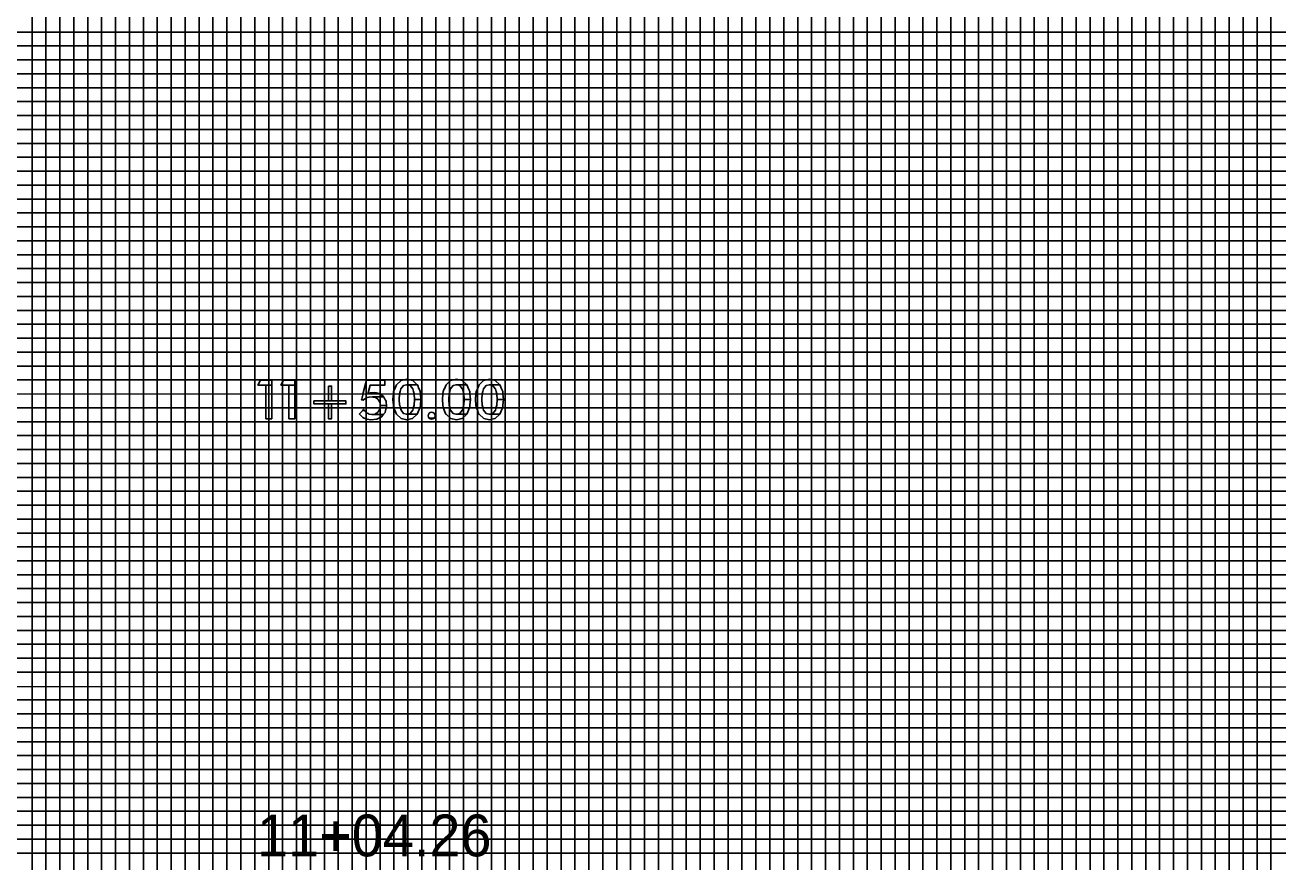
# Model space of a CAD drawing. Extents: x -13 to 323, y -5 to 1431.
# Drawn here: x 134.5 to 224.5, y 44.4 to 104.5 of the extents above; entities that cross this region are included whole.
import ezdxf

# ---------------------------------------------------------------- set-up
doc = ezdxf.new("R2010")
doc.units = 0
for name, color, linetype in [('Prop XS Station Labels', 7, 'Continuous'), ('Scratch_Level_3', 7, 'Continuous'), ('Sheet Cross Section Grid Major CELL', 7, 'Continuous'), ('Sheet Cross Section Grid Middle CELL', 7, 'Continuous'), ('Sheet Cross Section Grid Minor 1 CELL', 7, 'Continuous'), ('Sheet Cross Section Grid Minor 2 CELL', 7, 'Continuous'), ('Sheet DOT Grid CELL', 7, 'Continuous')]:
    doc.layers.add(name, color=color, linetype=linetype)

msp = doc.modelspace()

# ---------------------------------------------------------------- linework, layer by layer
at = {"layer": 'Prop XS Station Labels'}
for points in [[(151.405, 78.994), (151.226, 78.63), (152.224, 78.63), (152.224, 78.994)], [(151.805, 78.63), (151.805, 76.213), (152.224, 76.213), (152.224, 78.63)], [(153.059, 78.994), (152.881, 78.63), (153.878, 78.63), (153.878, 78.994)], [(153.46, 78.63), (153.46, 76.213), (153.878, 76.213), (153.878, 78.63)], [(156.291, 78.554), (156.291, 77.497), (156.518, 77.497), (156.518, 78.554)], [(158.679, 77.592), (158.674, 77.568), (158.814, 77.568), (158.84, 77.592), (158.873, 77.621), (159.015, 77.706), (159.078, 77.726), (159.218, 77.77), (159.447, 77.783), (160.263, 77.783), (160.246, 77.813), (159.978, 78.003), (159.135, 78.003), (159.141, 78.029), (159.141, 78.029), (159.151, 78.068), (159.3, 78.625), (160.351, 78.625), (160.351, 78.994), (159.025, 78.994), (158.934, 78.625), (158.796, 78.068), (158.787, 78.029), (158.78, 78.003), (158.734, 77.813), (158.726, 77.783), (158.723, 77.77), (158.712, 77.726), (158.707, 77.706), (158.686, 77.621)], [(161.527, 76.222), (161.926, 76.14), (162.315, 76.222), (162.337, 76.226), (162.668, 76.53), (161.92, 76.53), (161.9, 76.535), (161.891, 76.538), (161.682, 76.597), (161.507, 76.823), (161.507, 76.825), (161.506, 76.825), (161.451, 77.027), (161.45, 77.031), (161.41, 77.176), (161.408, 77.185), (161.373, 77.59), (161.373, 77.594), (161.373, 77.599), (161.408, 78.003), (161.45, 78.156), (161.45, 78.161), (161.504, 78.357), (161.505, 78.363), (161.682, 78.592), (161.907, 78.651), (161.915, 78.653), (161.935, 78.658), (162.675, 78.658), (162.349, 78.957), (162.332, 78.961), (161.931, 79.049), (161.93, 79.049), (161.515, 78.961), (161.51, 78.957), (161.188, 78.658), (161.182, 78.653), (161.18, 78.651), (161.155, 78.592), (161.061, 78.363), (161.059, 78.357), (160.978, 78.161), (160.977, 78.156), (160.961, 78.003), (160.919, 77.599), (160.918, 77.594), (160.919, 77.59), (160.959, 77.185), (160.96, 77.176), (160.975, 77.031), (160.975, 77.027), (161.058, 76.825), (161.059, 76.823), (161.151, 76.597), (161.175, 76.538), (161.176, 76.535), (161.182, 76.53), (161.522, 76.226)], [(162.449, 78.003), (162.482, 77.599), (162.936, 77.599), (162.896, 78.003), (162.882, 78.156), (162.88, 78.161), (162.88, 78.161), (162.801, 78.357), (162.8, 78.357), (162.798, 78.363), (162.706, 78.592), (162.706, 78.592), (162.682, 78.651), (162.682, 78.653), (162.675, 78.658), (161.935, 78.658), (161.955, 78.653), (161.961, 78.651), (162.175, 78.592), (162.35, 78.363), (162.355, 78.357), (162.407, 78.161), (162.408, 78.156)], [(165.086, 76.222), (165.485, 76.14), (165.875, 76.222), (165.896, 76.226), (166.227, 76.53), (165.479, 76.53), (165.46, 76.535), (165.45, 76.538), (165.241, 76.597), (165.066, 76.823), (165.066, 76.825), (165.065, 76.825), (165.01, 77.027), (165.01, 77.031), (164.97, 77.176), (164.967, 77.185), (164.932, 77.59), (164.932, 77.594), (164.932, 77.599), (164.967, 78.003), (165.009, 78.156), (165.01, 78.161), (165.063, 78.357), (165.065, 78.363), (165.241, 78.592), (165.466, 78.651), (165.474, 78.653), (165.495, 78.658), (166.235, 78.658), (165.908, 78.957), (165.891, 78.961), (165.49, 79.049), (165.49, 79.049), (165.074, 78.961), (165.07, 78.957), (164.747, 78.658), (164.741, 78.653), (164.739, 78.651), (164.715, 78.592), (164.62, 78.363), (164.618, 78.357), (164.537, 78.161), (164.536, 78.156), (164.52, 78.003), (164.478, 77.599), (164.477, 77.594), (164.478, 77.59), (164.518, 77.185), (164.519, 77.176), (164.534, 77.031), (164.535, 77.027), (164.617, 76.825), (164.618, 76.823), (164.71, 76.597), (164.734, 76.538), (164.735, 76.535), (164.741, 76.53), (165.081, 76.226)], [(166.008, 78.003), (166.041, 77.599), (166.495, 77.599), (166.455, 78.003), (166.441, 78.156), (166.439, 78.161), (166.439, 78.161), (166.36, 78.357), (166.36, 78.357), (166.357, 78.363), (166.265, 78.592), (166.265, 78.592), (166.241, 78.651), (166.241, 78.653), (166.235, 78.658), (165.495, 78.658), (165.514, 78.653), (165.52, 78.651), (165.734, 78.592), (165.909, 78.363), (165.914, 78.357), (165.966, 78.161), (165.967, 78.156)], [(167.459, 76.222), (167.858, 76.14), (168.247, 76.222), (168.269, 76.226), (168.6, 76.53), (167.852, 76.53), (167.832, 76.535), (167.823, 76.538), (167.614, 76.597), (167.439, 76.823), (167.439, 76.825), (167.438, 76.825), (167.383, 77.027), (167.382, 77.031), (167.342, 77.176), (167.34, 77.185), (167.305, 77.59), (167.305, 77.594), (167.305, 77.599), (167.34, 78.003), (167.381, 78.156), (167.382, 78.161), (167.435, 78.357), (167.437, 78.363), (167.614, 78.592), (167.839, 78.651), (167.846, 78.653), (167.867, 78.658), (168.607, 78.658), (168.281, 78.957), (168.264, 78.961), (167.863, 79.049), (167.862, 79.049), (167.446, 78.961), (167.442, 78.957), (167.12, 78.658), (167.114, 78.653), (167.112, 78.651), (167.087, 78.592), (166.993, 78.363), (166.99, 78.357), (166.91, 78.161), (166.909, 78.156), (166.893, 78.003), (166.85, 77.599), (166.85, 77.594), (166.85, 77.59), (166.891, 77.185), (166.892, 77.176), (166.907, 77.031), (166.907, 77.027), (166.99, 76.825), (166.99, 76.823), (167.083, 76.597), (167.107, 76.538), (167.108, 76.535), (167.114, 76.53), (167.454, 76.226)], [(168.381, 78.003), (168.414, 77.599), (168.868, 77.599), (168.828, 78.003), (168.814, 78.156), (168.812, 78.161), (168.811, 78.161), (168.733, 78.357), (168.732, 78.357), (168.73, 78.363), (168.638, 78.592), (168.638, 78.592), (168.614, 78.651), (168.614, 78.653), (168.607, 78.658), (167.867, 78.658), (167.887, 78.653), (167.893, 78.651), (168.106, 78.592), (168.281, 78.363), (168.286, 78.357), (168.339, 78.161), (168.34, 78.156)], [(155.255, 77.497), (155.255, 77.27), (157.554, 77.27), (157.554, 77.497)], [(158.673, 77.568), (158.789, 77.545), (158.814, 77.568)], [(159.21, 78.029), (159.135, 78.003), (159.978, 78.003), (159.942, 78.029), (159.746, 78.068), (159.325, 78.068)], [(159.6, 78.097), (159.325, 78.068), (159.746, 78.068), (159.601, 78.097)], [(159.991, 77.394), (160.035, 77.154), (160.46, 77.154), (160.439, 77.394), (160.439, 77.394), (160.432, 77.475), (160.393, 77.545), (160.381, 77.568), (160.368, 77.592), (160.352, 77.621), (160.305, 77.706), (160.294, 77.726), (160.27, 77.77), (160.263, 77.783), (159.447, 77.783), (159.5, 77.77), (159.682, 77.726), (159.71, 77.706), (159.831, 77.621), (159.873, 77.592), (159.887, 77.568), (159.9, 77.545), (159.942, 77.475)], [(161.94, 76.535), (161.92, 76.53), (162.668, 76.53), (162.674, 76.535), (162.677, 76.538), (162.701, 76.597), (162.795, 76.823), (162.796, 76.825), (162.879, 77.027), (162.881, 77.031), (162.895, 77.176), (162.896, 77.185), (162.936, 77.59), (162.936, 77.594), (162.936, 77.599), (162.481, 77.599), (162.481, 77.594), (162.481, 77.59), (162.449, 77.185), (162.448, 77.176), (162.409, 77.031), (162.408, 77.027), (162.354, 76.825), (162.352, 76.823), (162.175, 76.597), (161.951, 76.538)], [(165.5, 76.535), (165.479, 76.53), (166.227, 76.53), (166.233, 76.535), (166.236, 76.538), (166.26, 76.597), (166.354, 76.823), (166.355, 76.825), (166.438, 77.027), (166.44, 77.031), (166.454, 77.176), (166.455, 77.185), (166.495, 77.59), (166.495, 77.594), (166.495, 77.599), (166.04, 77.599), (166.04, 77.594), (166.04, 77.59), (166.008, 77.185), (166.007, 77.176), (165.968, 77.031), (165.967, 77.027), (165.913, 76.825), (165.911, 76.823), (165.734, 76.597), (165.51, 76.538)], [(167.872, 76.535), (167.852, 76.53), (168.6, 76.53), (168.606, 76.535), (168.609, 76.538), (168.633, 76.597), (168.727, 76.823), (168.728, 76.825), (168.811, 77.027), (168.813, 77.031), (168.827, 77.176), (168.828, 77.185), (168.868, 77.59), (168.868, 77.594), (168.868, 77.599), (168.413, 77.599), (168.413, 77.594), (168.413, 77.59), (168.38, 77.185), (168.38, 77.176), (168.34, 77.031), (168.34, 77.027), (168.285, 76.825), (168.284, 76.823), (168.106, 76.597), (167.883, 76.538)], [(156.291, 77.27), (156.291, 76.213), (156.518, 76.213), (156.518, 77.27)], [(159.077, 76.179), (159.348, 76.14), (159.744, 76.179), (159.76, 76.187), (160.007, 76.307), (160.007, 76.307), (160.106, 76.355), (160.195, 76.463), (160.234, 76.511), (159.411, 76.511), (159.192, 76.549), (159.188, 76.551), (159.183, 76.553), (159.017, 76.645), (158.997, 76.666), (158.985, 76.678), (158.985, 76.678), (158.884, 76.783), (158.819, 76.883), (158.819, 76.883), (158.728, 76.783), (158.634, 76.678), (158.623, 76.666), (158.604, 76.645), (158.521, 76.553), (158.519, 76.551), (158.52, 76.549), (158.551, 76.511), (158.589, 76.463), (158.716, 76.355), (158.773, 76.307), (159.021, 76.187)], [(159.625, 76.549), (159.411, 76.511), (160.234, 76.511), (160.265, 76.549), (160.266, 76.551), (160.269, 76.553), (160.268, 76.553), (160.344, 76.645), (160.361, 76.666), (160.364, 76.678), (160.393, 76.783), (160.423, 76.893), (160.469, 77.06), (160.46, 77.154), (160.035, 77.154), (160.019, 77.06), (159.99, 76.893), (159.92, 76.783), (159.853, 76.678), (159.833, 76.666), (159.8, 76.645), (159.651, 76.553), (159.635, 76.551)], [(163.475, 76.331), (163.529, 76.25), (163.885, 76.25), (163.938, 76.331), (163.957, 76.426), (163.938, 76.523), (163.885, 76.603), (163.803, 76.657), (163.706, 76.676), (163.61, 76.657), (163.529, 76.603), (163.475, 76.523), (163.455, 76.426)], [(163.61, 76.194), (163.706, 76.176), (163.803, 76.194), (163.885, 76.25), (163.529, 76.25)]]:
    msp.add_lwpolyline(points, close=True, dxfattribs=at)
at = {"layer": 'Scratch_Level_3'}
for points in [[(20, 110), (300, 110), (300, 80), (20, 80)], [(20, 75), (300, 75), (300, 45), (20, 45)]]:
    msp.add_lwpolyline(points, close=True, dxfattribs=at)
at = {"layer": 'Sheet Cross Section Grid Major CELL'}
for p, q in [((140, 210), (140, 0)), ((150, 0), (150, 210)), ((160, 210), (160, 0)), ((170, 0), (170, 210)), ((180, 210), (180, 0)), ((190, 0), (190, 210)), ((200, 210), (200, 0)), ((210, 0), (210, 210)), ((220, 210), (220, 0))]:
    msp.add_line(p, q, dxfattribs=at)
for points in [[(0, 100), (320, 100), (320, 90), (0, 90)], [(0, 80), (320, 80), (320, 70), (0, 70)], [(0, 60), (320, 60), (320, 50), (0, 50)]]:
    msp.add_lwpolyline(points, dxfattribs=at)
at = {"layer": 'Sheet Cross Section Grid Middle CELL'}
for points in [[(125, 0), (135, 0), (135, 210)], [(145, 210), (145, 0), (155, 0), (155, 210)], [(165, 210), (165, 0), (175, 0), (175, 210)], [(185, 210), (185, 0), (195, 0), (195, 210)], [(205, 210), (205, 0), (215, 0), (215, 210)], [(0, 85), (320, 85), (320, 95), (0, 95)], [(0, 65), (320, 65), (320, 75), (0, 75)], [(0, 45), (320, 45), (320, 55), (0, 55)]]:
    msp.add_lwpolyline(points, dxfattribs=at)
at = {"layer": 'Sheet Cross Section Grid Minor 1 CELL'}
for points in [[(0, 104), (320, 104), (320, 103), (0, 103)], [(0, 102), (320, 102), (320, 101), (0, 101)], [(0, 99), (320, 99), (320, 98), (0, 98)], [(0, 97), (320, 97), (320, 96), (0, 96)], [(0, 94), (320, 94), (320, 93), (0, 93)], [(0, 92), (320, 92), (320, 91), (0, 91)], [(0, 89), (320, 89), (320, 88), (0, 88)], [(0, 87), (320, 87), (320, 86), (0, 86)], [(0, 84), (320, 84), (320, 83), (0, 83)], [(0, 82), (320, 82), (320, 81), (0, 81)], [(0, 79), (320, 79), (319.99, 77.98), (0, 78)], [(0, 77), (320, 77), (320, 76), (0, 76)], [(0, 74), (320, 74), (320, 73), (0, 73)], [(0, 72), (320, 72), (320, 71), (0, 71)], [(0, 69), (320, 69), (320, 68), (0, 68)], [(0, 67), (320, 67), (320, 66), (0, 66)], [(0, 64), (320, 64), (320, 63), (0, 63)], [(0, 62), (320, 62), (320, 61), (0, 61)], [(0, 59), (320, 59), (320, 58), (0, 58)], [(0, 56.99), (320.07, 56.91), (320, 56), (0, 56)], [(0, 54), (320, 54), (320, 53), (0, 53)], [(0, 52), (320, 52), (320, 51), (0, 51)], [(0, 49), (320, 49), (320, 48), (0, 48)], [(0, 47), (320, 47), (320, 46), (0, 46)]]:
    msp.add_lwpolyline(points, dxfattribs=at)
at = {"layer": 'Sheet Cross Section Grid Minor 2 CELL'}
for points in [[(135, 0), (136, 0), (136, 210), (137, 210), (137, 0)], [(137, 0), (138, 0), (138, 210), (139, 210), (139, 0)], [(140, 0), (141, 0), (141, 210), (142, 210), (142, 0)], [(142, 0), (143, 0), (143, 210), (144, 210), (144, 0)], [(145, 0), (146, 0), (146, 210), (147, 210), (147, 0)], [(147, 0), (148, 0), (148, 210), (149, 210), (149, 0)], [(150, 0), (151, 0), (151, 210), (152, 210), (152, 0)], [(152, 0), (153, 0), (153, 210), (154, 210), (154, 0)], [(155, 0), (156, 0), (156, 210), (157, 210), (157, 0)], [(157, 0), (158, 0), (158, 210), (159, 210), (159, 0)], [(160, 0), (161, 0), (161, 210), (162, 210), (162, 0)], [(162, 0), (163, 0), (163, 210), (164, 210), (164, 0)], [(165, 0), (166, 0), (166, 210), (167, 210), (167, 0)], [(167, 0), (168, 0), (168, 210), (169, 210), (169, 0)], [(170, 0), (171, 0), (171, 210), (172, 210), (172, 0)], [(172, 0), (173, 0), (173, 210), (174, 210), (174, 0)], [(175, 0), (176, 0), (176, 210), (177, 210), (177, 0)], [(177, 0), (178, 0), (178, 210), (179, 210), (179, 0)], [(180, 0), (181, 0), (181, 210), (182, 210), (182, 0)], [(182, 0), (183, 0), (183, 210), (184, 210), (184, 0)], [(185, 0), (186, 0), (186, 210), (187, 210), (187, 0)], [(187, 0), (188, 0), (188, 210), (189, 210), (189, 0)], [(190, 0), (191, 0), (191, 210), (192, 210), (192, 0)], [(192, 0), (193, 0), (193, 210), (194, 210), (194, 0)], [(195, 0), (196, 0), (196, 210), (197, 210), (197, 0)], [(197, 0), (198, 0), (198, 210), (199, 210), (199, 0)], [(200, 0), (201, 0), (201, 210), (202, 210), (202, 0)], [(202, 0), (203, 0), (203, 210), (204, 210), (204, 0)], [(205, 0), (206, 0), (206, 210), (207, 210), (207, 0)], [(207, 0), (208, 0), (208, 210), (209, 210), (209, 0)], [(210, 0), (211, 0), (211, 210), (212, 210), (212, 0)], [(212, 0), (213, 0), (213, 210), (214, 210), (214, 0)], [(215, 0), (216, 0), (216, 210), (217, 210), (217, 0)], [(217, 0), (218, 0), (218, 210), (219, 210), (219, 0)], [(220, 0), (221, 0), (221, 210), (222, 210), (222, 0)], [(222, 0), (223, 0), (223, 210), (224, 210), (224, 0)]]:
    msp.add_lwpolyline(points, dxfattribs=at)
at = {"layer": 'Sheet DOT Grid CELL'}
for p, q in [((140, 0), (140, 210)), ((150, 0), (150, 210)), ((160, 0), (160, 210)), ((170, 0), (170, 210)), ((180, 0), (180, 210)), ((190, 0), (190, 210)), ((200, 0), (200, 210)), ((210, 0), (210, 210)), ((220, 0), (220, 210)), ((0, 100), (320, 100)), ((0, 90), (320, 90)), ((0, 80), (320, 80)), ((0, 70), (320, 70)), ((0, 60), (320, 60)), ((0, 50), (320, 50))]:
    msp.add_line(p, q, dxfattribs=at)

# ---------------------------------------------------------------- texts
at = {"layer": 'Prop XS Station Labels'}
msp.add_text('11+04.26', height=3, dxfattribs=at).set_placement((151.161, 44.768))

doc.saveas('drawing.dxf')
